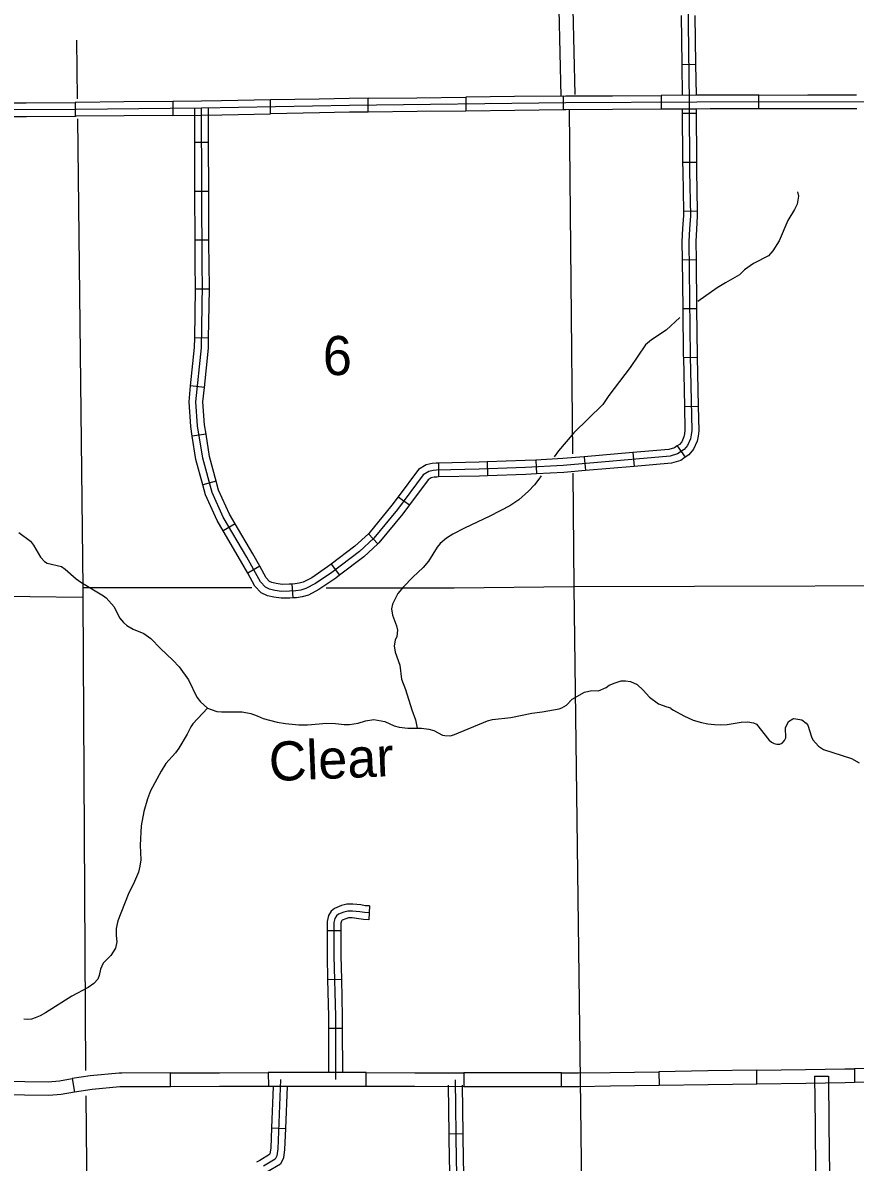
# Model space of a CAD drawing. Extents: x 1373862 to 1376999, y 1168398 to 1170455.
# Drawn here: x 1374915.6 to 1375095.6, y 1169193.7 to 1169439.9 of the extents above; entities that cross this region are included whole.
import ezdxf

# ---------------------------------------------------------------- set-up
doc = ezdxf.new("R2010")
doc.units = 0
for name, color, linetype in [('Level 31', 7, 'Continuous'), ('Level 32', 7, 'Continuous'), ('Level 35', 7, 'Continuous'), ('Level 4', 7, 'Continuous'), ('Level 5', 7, 'Continuous')]:
    doc.layers.add(name, color=color, linetype=linetype)

msp = doc.modelspace()

# ---------------------------------------------------------------- linework, layer by layer
at = {"layer": 'Level 31'}
for p, q in [((1375053.62, 1169424.21), (1375053.64, 1169421.21)), ((1375074.75, 1169421.29), (1375074.74, 1169424.29)), ((1375074.74, 1169424.29), (1375074.74, 1169424.29)), ((1374926.91, 1169422.68), (1374926.93, 1169419.68)), ((1374948.02, 1169422.88), (1374948.05, 1169419.88)), ((1374969.18, 1169420.22), (1374969.13, 1169423.22)), ((1374990.29, 1169420.59), (1374990.25, 1169423.59)), ((1375011.37, 1169423.83), (1375011.41, 1169420.83)), ((1375032.52, 1169421.07), (1375032.49, 1169424.07)), ((1374947.57, 1169209.96), (1374947.55, 1169212.96)), ((1374968.67, 1169213.05), (1374968.69, 1169210.05)), ((1374989.8, 1169210.02), (1374989.8, 1169213.02)), ((1375010.92, 1169212.98), (1375010.92, 1169209.98)), ((1375032.04, 1169209.96), (1375032.04, 1169212.96)), ((1375053.13, 1169213.22), (1375053.18, 1169210.22)), ((1375074.3, 1169210.53), (1375074.25, 1169213.53)), ((1375095.37, 1169213.85), (1375095.42, 1169210.85)), ((1374926.27, 1169211.72), (1374926.76, 1169208.76)), ((1375086.75, 1169212.23), (1375089.75, 1169212.26))]:
    msp.add_line(p, q, dxfattribs=at)
for points in [[(1375032.02, 1169424.07), (1375031.57, 1169442.77), (1375031.55, 1169443.68)], [(1375035.01, 1169424.39), (1375034.57, 1169442.83), (1375034.55, 1169443.72)], [(1375032.49, 1169424.07), (1375032.96, 1169424.08), (1375043.06, 1169424.14)], [(1375043.06, 1169424.14), (1375053.62, 1169424.21)], [(1375064.18, 1169424.27), (1375061.32, 1169424.26), (1375053.62, 1169424.21)], [(1375074.74, 1169424.29), (1375064.18, 1169424.27)], [(1375074.74, 1169424.29), (1375085.3, 1169424.31)], [(1375085.3, 1169424.31), (1375095.86, 1169424.33)], [(1375108.59, 1169422.85), (1375061.33, 1169422.76), (1375032.98, 1169422.58), (1374986.2, 1169422.05), (1374954.26, 1169421.43), (1374927.12, 1169421.19), (1374911.97, 1169421.07), (1374874.46, 1169421.18)], [(1374905.8, 1169422.59), (1374911.97, 1169422.57), (1374916.35, 1169422.6)], [(1374916.35, 1169422.6), (1374926.91, 1169422.68)], [(1374937.46, 1169422.78), (1374927.11, 1169422.69), (1374926.91, 1169422.68)], [(1374948.02, 1169422.88), (1374937.46, 1169422.78)], [(1374958.57, 1169423.01), (1374954.24, 1169422.93), (1374948.02, 1169422.88)], [(1374969.13, 1169423.22), (1374958.57, 1169423.01)], [(1374979.68, 1169423.42), (1374969.13, 1169423.22)], [(1374990.25, 1169423.59), (1374986.18, 1169423.55), (1374979.68, 1169423.42)], [(1374990.25, 1169423.59), (1375000.81, 1169423.71)], [(1375000.81, 1169423.71), (1375011.37, 1169423.83)], [(1375021.93, 1169423.95), (1375011.37, 1169423.83)], [(1375032.49, 1169424.07), (1375021.93, 1169423.95)], [(1374916.37, 1169419.6), (1374911.98, 1169419.57), (1374905.79, 1169419.59)], [(1374926.93, 1169419.68), (1374916.37, 1169419.6)], [(1374937.49, 1169419.78), (1374927.13, 1169419.69), (1374926.93, 1169419.68)], [(1374948.05, 1169419.88), (1374937.49, 1169419.78)], [(1374948.05, 1169419.88), (1374954.28, 1169419.93), (1374958.62, 1169420.02)], [(1374958.62, 1169420.02), (1374969.18, 1169420.22)], [(1374979.74, 1169420.42), (1374969.18, 1169420.22)], [(1374990.29, 1169420.59), (1374986.23, 1169420.55), (1374979.74, 1169420.42)], [(1375000.85, 1169420.71), (1374990.29, 1169420.59)], [(1375011.41, 1169420.83), (1375000.85, 1169420.71)], [(1375021.97, 1169420.95), (1375011.41, 1169420.83)], [(1375032.52, 1169421.07), (1375021.97, 1169420.95)], [(1375043.08, 1169421.14), (1375032.99, 1169421.08), (1375032.52, 1169421.07)], [(1375053.64, 1169421.21), (1375043.08, 1169421.14)], [(1375064.19, 1169421.27), (1375061.34, 1169421.26), (1375053.64, 1169421.21)], [(1375074.75, 1169421.29), (1375064.19, 1169421.27)], [(1375085.31, 1169421.31), (1375074.75, 1169421.29)], [(1375095.87, 1169421.33), (1375085.31, 1169421.31)], [(1374936.99, 1169212.92), (1374936.43, 1169212.92), (1374930.2, 1169212.35), (1374926.27, 1169211.72)], [(1374947.55, 1169212.96), (1374936.99, 1169212.92)], [(1374947.55, 1169212.96), (1374958.11, 1169213)], [(1374958.11, 1169213), (1374968.67, 1169213.05)], [(1374979.24, 1169213.04), (1374970.31, 1169213.05), (1374968.67, 1169213.05)], [(1374989.8, 1169213.02), (1374979.24, 1169213.04)], [(1374989.8, 1169213.02), (1375000.36, 1169213)], [(1375000.36, 1169213), (1375010.92, 1169212.98)], [(1375021.48, 1169212.97), (1375015.46, 1169212.97), (1375010.92, 1169212.98)], [(1375032.04, 1169212.96), (1375021.48, 1169212.97)], [(1375032.04, 1169212.96), (1375035.75, 1169212.96), (1375042.58, 1169213.06)], [(1375042.58, 1169213.06), (1375053.13, 1169213.22)], [(1375063.69, 1169213.38), (1375053.13, 1169213.22)], [(1375074.25, 1169213.53), (1375063.69, 1169213.38)], [(1375074.25, 1169213.53), (1375084.81, 1169213.69)], [(1375084.81, 1169213.69), (1375093.31, 1169213.82), (1375095.37, 1169213.85)], [(1375105.93, 1169214.03), (1375095.37, 1169213.85)], [(1374905.46, 1169211.26), (1374916.02, 1169211.12)], [(1374916.02, 1169211.12), (1374921.1, 1169211.05), (1374923.51, 1169211.27), (1374926.27, 1169211.72)], [(1374937.01, 1169209.92), (1374936.57, 1169209.92), (1374930.58, 1169209.38), (1374926.76, 1169208.76)], [(1374947.57, 1169209.96), (1374937.01, 1169209.92)], [(1374958.13, 1169210), (1374947.57, 1169209.96)], [(1374968.69, 1169210.05), (1374958.13, 1169210)], [(1374979.24, 1169210.04), (1374970.32, 1169210.05), (1374968.69, 1169210.05)], [(1374989.8, 1169210.02), (1374979.24, 1169210.04)], [(1375000.36, 1169210), (1374989.8, 1169210.02)], [(1375010.92, 1169209.98), (1375000.36, 1169210)], [(1375021.48, 1169209.97), (1375015.46, 1169209.97), (1375010.92, 1169209.98)], [(1375032.04, 1169209.96), (1375021.48, 1169209.97)], [(1375042.62, 1169210.06), (1375035.78, 1169209.96), (1375032.04, 1169209.96)], [(1375053.18, 1169210.22), (1375042.62, 1169210.06)], [(1375063.74, 1169210.38), (1375053.18, 1169210.22)], [(1375074.3, 1169210.53), (1375063.74, 1169210.38)], [(1375084.86, 1169210.69), (1375074.3, 1169210.53)], [(1375095.42, 1169210.85), (1375093.36, 1169210.82), (1375084.86, 1169210.69)], [(1375086.75, 1169212.23), (1375086.86, 1169201.67)], [(1375089.75, 1169212.26), (1375089.86, 1169201.7)], [(1375105.98, 1169211.03), (1375095.42, 1169210.85)], [(1374915.98, 1169208.12), (1374905.42, 1169208.26)], [(1374926.76, 1169208.76), (1374923.88, 1169208.29), (1374921.21, 1169208.05), (1374915.98, 1169208.12)], [(1375086.86, 1169201.67), (1375086.97, 1169191.11)], [(1375089.86, 1169201.7), (1375089.97, 1169191.14)]]:
    msp.add_lwpolyline(points, dxfattribs=at)
at = {"layer": 'Level 32'}
for p, q in [((1375058.06, 1169430.9), (1375061.06, 1169430.94)), ((1375058.19, 1169420.35), (1375061.19, 1169420.37)), ((1374955.78, 1169414.02), (1374952.78, 1169414.01)), ((1375058.25, 1169409.79), (1375061.25, 1169409.81)), ((1374955.81, 1169403.46), (1374952.81, 1169403.45)), ((1375058.41, 1169399.22), (1375061.41, 1169399.27)), ((1374955.84, 1169392.9), (1374952.84, 1169392.89)), ((1375058.14, 1169388.68), (1375061.14, 1169388.71)), ((1374955.94, 1169382.31), (1374952.94, 1169382.36)), ((1375058.27, 1169378.12), (1375061.27, 1169378.15)), ((1374955.76, 1169371.75), (1374952.76, 1169371.8)), ((1375058.4, 1169367.55), (1375061.4, 1169367.61)), ((1374954.87, 1169361.11), (1374951.88, 1169361.41)), ((1375058.62, 1169356.99), (1375061.62, 1169357.05)), ((1374955.21, 1169350.98), (1374952.24, 1169350.53)), ((1375057.07, 1169348.46), (1375058.78, 1169346)), ((1375026.5, 1169345.4), (1375026.65, 1169342.41)), ((1375036.98, 1169346.11), (1375037.24, 1169343.12)), ((1375047.5, 1169347.02), (1375047.76, 1169344.03)), ((1375005.44, 1169344.74), (1375005.5, 1169341.74)), ((1375015.97, 1169344.99), (1375016.08, 1169341.99)), ((1374957.4, 1169340.85), (1374954.51, 1169340.06)), ((1374996.78, 1169337.48), (1374999.19, 1169335.69)), ((1374961.53, 1169331.6), (1374958.94, 1169330.09)), ((1374990.34, 1169329.48), (1374992.36, 1169327.26)), ((1374966.84, 1169322.44), (1374964.22, 1169320.97)), ((1374982.27, 1169322.89), (1374984.09, 1169320.51)), ((1374973.78, 1169318.6), (1374973.99, 1169315.6)), ((1374990.52, 1169249.04), (1374990.39, 1169246.04)), ((1374981.37, 1169243.76), (1374984.37, 1169243.76)), ((1374981.49, 1169233.17), (1374984.49, 1169233.24)), ((1374981.68, 1169222.64), (1374984.68, 1169222.65)), ((1374969.38, 1169201.06), (1374972.37, 1169200.94)), ((1375010.79, 1169199.78), (1375007.79, 1169199.75))]:
    msp.add_line(p, q, dxfattribs=at)
for points in [[(1375059.27, 1169451.11), (1375059.67, 1169422.73), (1375059.76, 1169407.84), (1375059.92, 1169398.18), (1375059.73, 1169395.35), (1375059.6, 1169392.63), (1375059.89, 1169367.85), (1375060.23, 1169351.79), (1375060.11, 1169350.82), (1375059.92, 1169349.96), (1375059.33, 1169348.55), (1375058.55, 1169347.66), (1375057.17, 1169346.71), (1375055.56, 1169346.21), (1375032.45, 1169344.21), (1375024.28, 1169343.78), (1375014.27, 1169343.42), (1375005.03, 1169343.23), (1375004.31, 1169343.16), (1375003.36, 1169342.96), (1375002.18, 1169342.24), (1374996.6, 1169334.72), (1374991.51, 1169328.51), (1374988.36, 1169325.66), (1374982.39, 1169321.09), (1374978.86, 1169318.69), (1374976.81, 1169317.61), (1374975.69, 1169317.28), (1374974.64, 1169317.15), (1374973.23, 1169317.05), (1374971.55, 1169317.02), (1374970.11, 1169317.22), (1374968.96, 1169317.48), (1374968.04, 1169317.91), (1374967.02, 1169319.06), (1374964.01, 1169324.41), (1374958.95, 1169333.05), (1374956.52, 1169338.37), (1374954.49, 1169345.83), (1374953.4, 1169352.83), (1374953.04, 1169357.99), (1374954.22, 1169369.64), (1374954.45, 1169383.29), (1374954.36, 1169387), (1374954.26, 1169421.43)], [(1375057.91, 1169441.46), (1375058.06, 1169430.9)], [(1375060.91, 1169441.5), (1375061.06, 1169430.94)], [(1375058.06, 1169430.9), (1375058.15, 1169424.24)], [(1375061.06, 1169430.94), (1375061.15, 1169424.26)], [(1374952.78, 1169414.01), (1374952.76, 1169421.43)], [(1374955.78, 1169414.02), (1374955.76, 1169421.44)], [(1375058.18, 1169421.24), (1375058.25, 1169409.79)], [(1375061.18, 1169421.26), (1375061.25, 1169409.81)], [(1374952.81, 1169403.45), (1374952.78, 1169414.01)], [(1374955.81, 1169403.46), (1374955.78, 1169414.02)], [(1375058.25, 1169409.79), (1375058.26, 1169407.83), (1375058.41, 1169399.22)], [(1375061.25, 1169409.81), (1375061.26, 1169407.86), (1375061.41, 1169399.27)], [(1374952.84, 1169392.89), (1374952.81, 1169403.45)], [(1374955.84, 1169392.9), (1374955.81, 1169403.46)], [(1375058.41, 1169399.22), (1375058.42, 1169398.22), (1375058.23, 1169395.44), (1375058.1, 1169392.66), (1375058.14, 1169388.68)], [(1375061.41, 1169399.27), (1375061.42, 1169398.14), (1375061.22, 1169395.27), (1375061.1, 1169392.6), (1375061.14, 1169388.71)], [(1374952.94, 1169382.36), (1374952.95, 1169383.28), (1374952.86, 1169386.98), (1374952.84, 1169392.89)], [(1374955.94, 1169382.31), (1374955.95, 1169383.3), (1374955.86, 1169387.02), (1374955.84, 1169392.9)], [(1375058.14, 1169388.68), (1375058.27, 1169378.12)], [(1375061.14, 1169388.71), (1375061.27, 1169378.15)], [(1374952.76, 1169371.8), (1374952.94, 1169382.36)], [(1374955.76, 1169371.75), (1374955.94, 1169382.31)], [(1375058.27, 1169378.12), (1375058.39, 1169367.82), (1375058.4, 1169367.55)], [(1375061.27, 1169378.15), (1375061.39, 1169367.87), (1375061.4, 1169367.61)], [(1374951.88, 1169361.41), (1374952.73, 1169369.73), (1374952.76, 1169371.8)], [(1374954.87, 1169361.11), (1374955.72, 1169369.56), (1374955.76, 1169371.75)], [(1375058.4, 1169367.55), (1375058.62, 1169356.99)], [(1375061.4, 1169367.61), (1375061.62, 1169357.05)], [(1374952.24, 1169350.53), (1374951.91, 1169352.66), (1374951.54, 1169358.01), (1374951.88, 1169361.41)], [(1374955.21, 1169350.98), (1374954.9, 1169353), (1374954.55, 1169357.96), (1374954.87, 1169361.11)], [(1375058.62, 1169356.99), (1375058.72, 1169351.86), (1375058.63, 1169351.07), (1375058.49, 1169350.41), (1375058.05, 1169349.36), (1375057.54, 1169348.79), (1375057.07, 1169348.46)], [(1375061.62, 1169357.05), (1375061.73, 1169351.71), (1375061.59, 1169350.57), (1375061.36, 1169349.51), (1375060.62, 1169347.74), (1375059.55, 1169346.53), (1375058.78, 1169346)], [(1374954.51, 1169340.06), (1374953.02, 1169345.51), (1374952.24, 1169350.53)], [(1374957.4, 1169340.85), (1374955.96, 1169346.14), (1374955.21, 1169350.98)], [(1375057.07, 1169348.46), (1375056.51, 1169348.07), (1375055.27, 1169347.7), (1375047.5, 1169347.02)], [(1375026.5, 1169345.4), (1375024.21, 1169345.28), (1375015.97, 1169344.99)], [(1375036.98, 1169346.11), (1375032.35, 1169345.71), (1375026.5, 1169345.4)], [(1375047.5, 1169347.02), (1375036.98, 1169346.11)], [(1375058.78, 1169346), (1375057.83, 1169345.34), (1375055.85, 1169344.73), (1375047.76, 1169344.03)], [(1375005.44, 1169344.74), (1375004.95, 1169344.72), (1375004.09, 1169344.65), (1375002.8, 1169344.38), (1375001.15, 1169343.37), (1374996.78, 1169337.48)], [(1375015.97, 1169344.99), (1375014.23, 1169344.92), (1375005.44, 1169344.74)], [(1375037.24, 1169343.12), (1375032.56, 1169342.71), (1375026.65, 1169342.41)], [(1375047.76, 1169344.03), (1375037.24, 1169343.12)], [(1374961.53, 1169331.6), (1374960.28, 1169333.74), (1374957.94, 1169338.88), (1374957.4, 1169340.85)], [(1375005.5, 1169341.74), (1375005.12, 1169341.73), (1375004.53, 1169341.67), (1375003.92, 1169341.55), (1375003.21, 1169341.11), (1374999.19, 1169335.69)], [(1375016.08, 1169341.99), (1375014.31, 1169341.92), (1375005.5, 1169341.74)], [(1375026.65, 1169342.41), (1375024.35, 1169342.29), (1375016.08, 1169341.99)], [(1374958.94, 1169330.09), (1374957.62, 1169332.35), (1374955.11, 1169337.86), (1374954.51, 1169340.06)], [(1374996.78, 1169337.48), (1374995.41, 1169335.64), (1374990.42, 1169329.55), (1374990.34, 1169329.48)], [(1374999.19, 1169335.69), (1374997.78, 1169333.8), (1374992.6, 1169327.48), (1374992.36, 1169327.26)], [(1374966.84, 1169322.44), (1374965.31, 1169325.16), (1374961.53, 1169331.6)], [(1374964.22, 1169320.97), (1374962.7, 1169323.66), (1374958.94, 1169330.09)], [(1374990.34, 1169329.48), (1374987.4, 1169326.81), (1374982.27, 1169322.89)], [(1374992.36, 1169327.26), (1374989.32, 1169324.5), (1374984.09, 1169320.51)], [(1374973.99, 1169315.6), (1374973.3, 1169315.56), (1374971.47, 1169315.52), (1374969.84, 1169315.74), (1374968.47, 1169316.05), (1374967.13, 1169316.68), (1374965.8, 1169318.18), (1374964.22, 1169320.97)], [(1374973.78, 1169318.6), (1374973.16, 1169318.55), (1374971.64, 1169318.52), (1374970.38, 1169318.7), (1374969.45, 1169318.91), (1374968.96, 1169319.14), (1374968.25, 1169319.93), (1374966.84, 1169322.44)], [(1374982.27, 1169322.89), (1374981.51, 1169322.31), (1374978.09, 1169319.98), (1374976.24, 1169319.01), (1374975.38, 1169318.76), (1374974.49, 1169318.65), (1374973.78, 1169318.6)], [(1374984.09, 1169320.51), (1374983.26, 1169319.88), (1374979.63, 1169317.4), (1374977.37, 1169316.22), (1374976, 1169315.81), (1374974.78, 1169315.66), (1374973.99, 1169315.6)], [(1374990.52, 1169249.04), (1374989.62, 1169249.08), (1374988.7, 1169249.25), (1374986.94, 1169249.44), (1374985.67, 1169249.44), (1374984.5, 1169249.14), (1374983.02, 1169248.52), (1374982.3, 1169247.88), (1374981.7, 1169246.97), (1374981.37, 1169245.66), (1374981.37, 1169243.76)], [(1374990.46, 1169247.54), (1374989.45, 1169247.59), (1374988.48, 1169247.76), (1374986.86, 1169247.94), (1374985.85, 1169247.94), (1374984.97, 1169247.72), (1374983.83, 1169247.23), (1374983.44, 1169246.88), (1374983.09, 1169246.36), (1374982.87, 1169245.48), (1374982.87, 1169238.24), (1374983.18, 1169225.16), (1374983.22, 1169211.53)], [(1374990.39, 1169246.04), (1374989.28, 1169246.09), (1374988.27, 1169246.28), (1374986.78, 1169246.44), (1374986.04, 1169246.44), (1374985.45, 1169246.29), (1374984.65, 1169245.95), (1374984.58, 1169245.89), (1374984.48, 1169245.74), (1374984.37, 1169245.29), (1374984.37, 1169243.76)], [(1374981.37, 1169243.76), (1374981.37, 1169238.22), (1374981.49, 1169233.17)], [(1374984.37, 1169243.76), (1374984.37, 1169238.25), (1374984.49, 1169233.24)], [(1374981.49, 1169233.17), (1374981.68, 1169225.14), (1374981.68, 1169222.64)], [(1374984.49, 1169233.24), (1374984.68, 1169225.18), (1374984.68, 1169222.65)], [(1374981.68, 1169222.64), (1374981.71, 1169213.03)], [(1374984.68, 1169222.65), (1374984.71, 1169213.03)], [(1374971.28, 1169211.55), (1374970.71, 1169196.56), (1374970.49, 1169195.06), (1374970.13, 1169194.31), (1374967.62, 1169192.77)], [(1374969.72, 1169210.05), (1374969.38, 1169201.06)], [(1374972.72, 1169210.05), (1374972.37, 1169200.94)], [(1375007.79, 1169199.75), (1375007.66, 1169210.31)], [(1375010.6, 1169157.56), (1375010.38, 1169171.48), (1375010.16, 1169182.67), (1375009.54, 1169189.43), (1375009.37, 1169193.9), (1375009.15, 1169211.48)], [(1375010.79, 1169199.78), (1375010.66, 1169210.34)], [(1374969.38, 1169201.06), (1374969.21, 1169196.69), (1374969.03, 1169195.5), (1374968.97, 1169195.35), (1374966.86, 1169194.06), (1374966.16, 1169193.66)], [(1374972.37, 1169200.94), (1374972.2, 1169196.42), (1374971.94, 1169194.62), (1374971.3, 1169193.27), (1374968.39, 1169191.48), (1374967.65, 1169191.06)], [(1375008.07, 1169189.07), (1375008.04, 1169189.33), (1375007.87, 1169193.87), (1375007.79, 1169199.75)], [(1375011.06, 1169189.35), (1375011.04, 1169189.52), (1375010.87, 1169193.94), (1375010.79, 1169199.78)]]:
    msp.add_lwpolyline(points, dxfattribs=at)
at = {"layer": 'Level 35'}
for points in [[(1375083.06, 1169403.36), (1375083.31, 1169402.4), (1375083.03, 1169400.71), (1375082.46, 1169399.55), (1375080.98, 1169397.2), (1375079.12, 1169392.8), (1375077.76, 1169390.59), (1375076.8, 1169389.53), (1375073.57, 1169387.87), (1375071.62, 1169386.54), (1375070.55, 1169385.41), (1375067.51, 1169383.72), (1375065.74, 1169382.61), (1375061.56, 1169379.67)], [(1375057.61, 1169376.18), (1375054.66, 1169373.46), (1375051.49, 1169371.35), (1375050.22, 1169370.28), (1375046.91, 1169365.43), (1375042.27, 1169359.33), (1375041.02, 1169357.43), (1375034.7, 1169351.3), (1375031.42, 1169347.42), (1375030.48, 1169346.07)], [(1375027.67, 1169342.02), (1375027.14, 1169341.25), (1375026.21, 1169340.06), (1375024.92, 1169338.7), (1375022.87, 1169336.84), (1375020.89, 1169335.53), (1375016.6, 1169333.3), (1375011.07, 1169330.65), (1375008.57, 1169329.36), (1375007.23, 1169328.5), (1375005.86, 1169327.34), (1375005.18, 1169326.6), (1375003.32, 1169323.58), (1375002.19, 1169322.21), (1374999.93, 1169320.08), (1374997.92, 1169318.02), (1374996.7, 1169316.58), (1374995.52, 1169314.26), (1374995.34, 1169313.24), (1374995.5, 1169311.88), (1374996.42, 1169309.59), (1374996.61, 1169308.63), (1374996.44, 1169307.29), (1374996.1, 1169306.47), (1374995.87, 1169305.22), (1374996.07, 1169303.87), (1374997.08, 1169301.08), (1374997.5, 1169298.05), (1374998.36, 1169295.78), (1374999.67, 1169291.44), (1375000.47, 1169289.24), (1375000.84, 1169287.46)], [(1374914.78, 1169329.75), (1374917.29, 1169327.88), (1374917.94, 1169326.99), (1374919.44, 1169324.44), (1374920.31, 1169323.5), (1374920.9, 1169323.1), (1374923.96, 1169322.4), (1374924.75, 1169321.84), (1374927.15, 1169319.73), (1374928.15, 1169318.98), (1374933.08, 1169316.08), (1374933.66, 1169315.62), (1374935.33, 1169313.69), (1374936.49, 1169311.3), (1374937.34, 1169310.3), (1374938.07, 1169309.65), (1374939.47, 1169308.83), (1374941.78, 1169307.93), (1374943.29, 1169306.85), (1374945.34, 1169304.67), (1374948.05, 1169302.18), (1374949.41, 1169300.71), (1374951.42, 1169297.94), (1374953.24, 1169294.15), (1374954, 1169293.15), (1374955.52, 1169291.77), (1374957.56, 1169291.08), (1374958.56, 1169290.98), (1374963.06, 1169290.98), (1374964.87, 1169290.61), (1374966.25, 1169290.09)], [(1374966.25, 1169290.09), (1374967.54, 1169289.54), (1374970.56, 1169288.74), (1374972.37, 1169288.45), (1374975.28, 1169288.18), (1374977.16, 1169288.17), (1374981.31, 1169288.52), (1374983.17, 1169288.47), (1374985.06, 1169288.24), (1374986.26, 1169288.24), (1374988.13, 1169288.53), (1374989.72, 1169289.03), (1374991.49, 1169289.32), (1374993.88, 1169288.88), (1374995.9, 1169287.97), (1374996.97, 1169287.68), (1374998.86, 1169287.47), (1375001.8, 1169287.45), (1375003.36, 1169287.25), (1375004.43, 1169286.98), (1375006.3, 1169285.98), (1375006.84, 1169285.84), (1375008.04, 1169285.81), (1375008.94, 1169286.07), (1375016.08, 1169289.05), (1375017.17, 1169289.34), (1375021.08, 1169289.73), (1375025.66, 1169290.7), (1375027.85, 1169290.97), (1375031.55, 1169291.62), (1375032.15, 1169291.83), (1375033.15, 1169292.4), (1375034.38, 1169293.72), (1375037, 1169295.23), (1375038.65, 1169295.6), (1375040.09, 1169295.5), (1375041.71, 1169296.24), (1375042.36, 1169296.76), (1375043.65, 1169297.26), (1375044.94, 1169297.67), (1375045.9, 1169297.7), (1375046.96, 1169297.55), (1375048.4, 1169296.92), (1375049.69, 1169295.69), (1375051.05, 1169294.18), (1375053.05, 1169292.69), (1375054.82, 1169292.04), (1375055.61, 1169291.86), (1375055.67, 1169291.72), (1375056.24, 1169291.35), (1375058.54, 1169290.09), (1375060.52, 1169289.22), (1375062.33, 1169288.67), (1375063.72, 1169288.38), (1375065.15, 1169288.22), (1375066.33, 1169288.15), (1375067.88, 1169288.26), (1375070.89, 1169288.78), (1375072.31, 1169288.82), (1375073.54, 1169288.59), (1375074.22, 1169288.3), (1375076.85, 1169284.92), (1375077.45, 1169284.42), (1375078.03, 1169284.11), (1375078.58, 1169284.01), (1375079.28, 1169284.03), (1375079.77, 1169284.22), (1375080.26, 1169284.78), (1375080.52, 1169285.34), (1375080.46, 1169287.55), (1375081.13, 1169288.93), (1375082.04, 1169289.46)], [(1374955.52, 1169291.77), (1374952.39, 1169288.39), (1374951.92, 1169287.78), (1374951.13, 1169286.15), (1374949.35, 1169283.11), (1374948.63, 1169282.11), (1374946.55, 1169279.79), (1374945.49, 1169278.18), (1374943.2, 1169273.94), (1374942.57, 1169272.16), (1374941.78, 1169269.47), (1374941.16, 1169266.36), (1374941.01, 1169262.17), (1374941.13, 1169259.04), (1374940.93, 1169257.61), (1374940.6, 1169256.32), (1374939.78, 1169254.33), (1374938.39, 1169251.54), (1374936.16, 1169245.85), (1374935.82, 1169244.19), (1374935.78, 1169242.67), (1374935.9, 1169241.29), (1374935.67, 1169239.92), (1374934.67, 1169238.34), (1374932.96, 1169236.69), (1374932.39, 1169235.37), (1374932.14, 1169234.04), (1374931.83, 1169233.25), (1374930.93, 1169232.29), (1374929.73, 1169231.45), (1374926.2, 1169229.55), (1374920.48, 1169225.93), (1374919.37, 1169225.3), (1374918.3, 1169224.85), (1374917.49, 1169224.58), (1374916.71, 1169224.5), (1374915.86, 1169224.55)], [(1375082.04, 1169289.46), (1375082.25, 1169289.52), (1375083.98, 1169289.29), (1375084.92, 1169288.55), (1375085.31, 1169288.1), (1375086.1, 1169285.61), (1375086.41, 1169284.92), (1375087.63, 1169283.57), (1375088.73, 1169282.86), (1375094.72, 1169280.87), (1375096.44, 1169279.95)]]:
    msp.add_lwpolyline(points, dxfattribs=at)
at = {"layer": 'Level 4'}
for points in [[(1374927.2, 1169436.13), (1374927.36, 1169423.43)], [(1374927.41, 1169419.17), (1374928.59, 1169317.78), (1374928.6, 1169315.72), (1374929.15, 1169213.46)], [(1374929.2, 1169207.98), (1374929.48, 1169185.76)]]:
    msp.add_lwpolyline(points, dxfattribs=at)
at = {"layer": 'Level 5'}
for points in [[(1375033.71, 1169421.08), (1375034.47, 1169346.77)], [(1375034.51, 1169342.59), (1375034.76, 1169317.98)], [(1375139, 1169318.31), (1375034.76, 1169317.98)], [(1374928.6, 1169315.72), (1374905.58, 1169316.01)], [(1374965.12, 1169317.76), (1374928.59, 1169317.78)], [(1375034.76, 1169317.98), (1375008.87, 1169317.73), (1374981.16, 1169317.75)], [(1375034.76, 1169317.98), (1375036.08, 1169211.47)], [(1375036.08, 1169211.47), (1375037.4, 1169106.13)]]:
    msp.add_lwpolyline(points, dxfattribs=at)

# ---------------------------------------------------------------- texts
at = {"layer": 'Level 35'}
msp.add_text('Clear', height=8.448, rotation=2.4036, dxfattribs=at).set_placement((1374968.97, 1169275.99))
at = {"layer": 'Level 5'}
msp.add_text('6', height=8.45, dxfattribs=at).set_placement((1374980.47, 1169363.76))

doc.saveas('drawing.dxf')
